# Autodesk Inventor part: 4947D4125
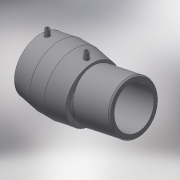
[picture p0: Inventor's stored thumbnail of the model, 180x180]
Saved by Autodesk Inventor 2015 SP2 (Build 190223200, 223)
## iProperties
Created: 2017-06
Part Number: 4947D4125
Material: Generic
Description: PLASSON ADJUSTABLE ELBOW (ONE SIDE) 125
Document SubType Name: Modeling
Designer: KIM
Mass: 1776.56 g
Surface Area: 2554.66 cm^2
Volume: 1776.56 cm^3
Density: 1 g/cm^3
Appearance: Default
Author: KIM
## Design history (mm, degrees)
derived "4947D4.ipt"
feature "Solid1::4947D4.ipt"
tag "TaggingFeature1"
body "Solid1"
other parameters: "d0" = 153.3, "d2" = 157, "d4" = 45, "d5" = 141.3, "d7" = 125, "d8" = 168 deg, "d10" = 36, "d11" = 12, "d29" = 95, "d30" = 15, "d31" = 58.4, "d34" = 5 deg, "d41" = 4, "d42" = 14, "d43" = 0, "d48" = 112.5, "d55" = 37.98, "d57" = 168 deg, "d62" = 3, "d63" = 0, "d65" = 292, "d66" = 125, "d67" = 112.5, "d68" = 135 deg, "d70" = 58.09, "d71" = 3.14, "d_" = 125, "L_" = 292, "D_" = 157, "A_" = 95, "d_2" = 12, "L_0" = 148, "D_1" = 125, "d54" = 63.3, "d59" = 177.35893
